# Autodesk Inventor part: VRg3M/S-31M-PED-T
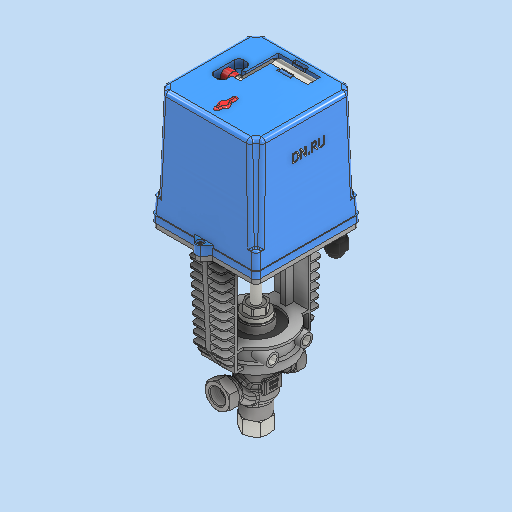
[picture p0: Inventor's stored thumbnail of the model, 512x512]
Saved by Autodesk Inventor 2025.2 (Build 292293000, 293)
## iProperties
Company: DN.RU
Created: 2026-04
Part Number: VRg3M/S-31M-PED-T
Material: Типовые
Document SubType Name: Modeling
Designer: DN.RU
Density: 1.28608 g/cm^3
Appearance: По умолчанию
Description: D230-11263
Mass: 3100 g
Surface Area: 2050.69 cm^2
Volume: 2410.43 cm^3
Author: DN.RU
Title: Клапан регулирующий трехходовой Ду15 Ру25
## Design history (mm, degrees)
derived "Сборка.iam"
feature "Резьба1" dims "d1" = 90, "d2" = 0
feature "Резьба2" dims "d3" = 16, "d4" = 0
node "Твердое тело1"
node "Деталь 1.ipt:1"
node "Деталь 2.ipt:1"
node "Деталь 3.ipt:1"
node "AS 1421 засверленный конец - метрическая M10 x 12 засверленн"
node "AS 1420 - метрическая M5 x 10:1"
node "AS 1420 - метрическая M5 x 10:2"
node "AS 1427 H - метрическая M3 x 8:1"
node "AS 1427 H - метрическая M3 x 8:2"
